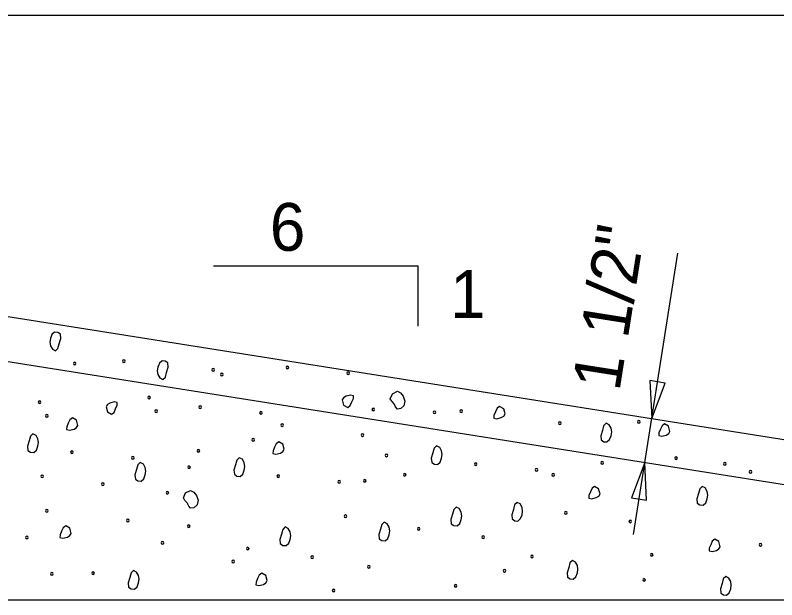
# Model space of a CAD drawing. Extents: x -439.1 to -407.9, y -458.1 to -436.2.
# Drawn here: x -421.545 to -419.155, y -448.319 to -446.484 of the extents above; entities that cross this region are included whole.
import ezdxf

# ---------------------------------------------------------------- set-up
doc = ezdxf.new("R2010")
doc.units = 0
doc.layers.add('Level 4', color=7, linetype='Continuous')
doc.layers.add('Level 45', color=7, linetype='Continuous')

msp = doc.modelspace()

# ---------------------------------------------------------------- linework, layer by layer
at = {"layer": 'Level 4'}
for p, q in [((-422.391, -446.484), (-416.8905, -446.484)), ((-423.8016, -447.0755), (-416.8905, -448.1707)), ((-419.6048, -448.1134), (-419.4651, -447.2309)), ((-420.9225, -447.2708), (-420.2799, -447.2708)), ((-420.2799, -447.4598), (-420.2799, -447.2708)), ((-421.8946, -447.5188), (-417.2694, -448.2521)), ((-423.8016, -448.3187), (-416.8905, -448.3187))]:
    msp.add_line(p, q, dxfattribs=at)
for points in [[(-421.4187, -447.5372), (-421.4108, -447.5297), (-421.407, -447.5151), (-421.4017, -447.4983), (-421.4031, -447.4852), (-421.4113, -447.4796), (-421.4213, -447.4788), (-421.4297, -447.4861), (-421.4343, -447.4982), (-421.4361, -447.51), (-421.4343, -447.5216), (-421.4283, -447.5324), (-421.4187, -447.5372)], [(-421.0817, -447.6272), (-421.0737, -447.6197), (-421.07, -447.6051), (-421.0647, -447.5883), (-421.0661, -447.5753), (-421.0743, -447.5697), (-421.0843, -447.5688), (-421.0927, -447.5761), (-421.0972, -447.5882), (-421.0991, -447.6), (-421.0972, -447.6116), (-421.0912, -447.6224), (-421.0817, -447.6272)], [(-419.5529, -447.631), (-419.5472, -447.7495), (-419.5052, -447.6386)], [(-420.5015, -447.7148), (-420.4937, -447.7089), (-420.4885, -447.6979), (-420.4838, -447.6867), (-420.4834, -447.6785), (-420.4928, -447.6761), (-420.5067, -447.6798), (-420.5145, -447.6845), (-420.5184, -447.6915), (-420.5142, -447.7074), (-420.5015, -447.7148)], [(-420.3678, -447.6877), (-420.3612, -447.672), (-420.3457, -447.6644), (-420.3354, -447.6692), (-420.3275, -447.6799), (-420.3218, -447.6952), (-420.3249, -447.7098), (-420.335, -447.7186), (-420.3457, -447.7202), (-420.3512, -447.7131), (-420.3561, -447.7033), (-420.3631, -447.6957), (-420.3678, -447.6877)], [(-421.2428, -447.7363), (-421.235, -447.7305), (-421.2298, -447.7195), (-421.225, -447.7082), (-421.2246, -447.7), (-421.2341, -447.6977), (-421.2479, -447.7013), (-421.2557, -447.7061), (-421.2596, -447.713), (-421.2554, -447.7289), (-421.2428, -447.7363)], [(-420.0246, -447.7119), (-420.0324, -447.7178), (-420.0376, -447.7288), (-420.0424, -447.74), (-420.0428, -447.7483), (-420.0333, -447.7506), (-420.0195, -447.747), (-420.0117, -447.7422), (-420.0078, -447.7353), (-420.012, -447.7194), (-420.0246, -447.7119)], [(-421.3656, -447.7479), (-421.3733, -447.7538), (-421.3785, -447.7648), (-421.3833, -447.776), (-421.3837, -447.7843), (-421.3743, -447.7866), (-421.3604, -447.783), (-421.3526, -447.7782), (-421.3487, -447.7713), (-421.3529, -447.7553), (-421.3656, -447.7479)], [(-419.6904, -447.7649), (-419.6983, -447.7724), (-419.7021, -447.787), (-419.7074, -447.8038), (-419.706, -447.8169), (-419.6978, -447.8225), (-419.6878, -447.8234), (-419.6794, -447.816), (-419.6748, -447.8039), (-419.673, -447.7921), (-419.6748, -447.7805), (-419.6808, -447.7697), (-419.6904, -447.7649)], [(-419.5071, -447.7667), (-419.5149, -447.7726), (-419.5201, -447.7836), (-419.5248, -447.7948), (-419.5253, -447.803), (-419.5158, -447.8054), (-419.5019, -447.8017), (-419.4941, -447.797), (-419.4902, -447.7901), (-419.4945, -447.7741), (-419.5071, -447.7667)], [(-421.4894, -447.798), (-421.4973, -447.8055), (-421.5011, -447.8201), (-421.5064, -447.8369), (-421.505, -447.8499), (-421.4968, -447.8555), (-421.4868, -447.8564), (-421.4784, -447.8491), (-421.4738, -447.837), (-421.472, -447.8252), (-421.4738, -447.8136), (-421.4798, -447.8028), (-421.4894, -447.798)], [(-420.7179, -447.823), (-420.7257, -447.8289), (-420.7309, -447.8399), (-420.7357, -447.8511), (-420.7361, -447.8594), (-420.7266, -447.8617), (-420.7127, -447.8581), (-420.705, -447.8533), (-420.701, -447.8464), (-420.7053, -447.8304), (-420.7179, -447.823)], [(-420.2223, -447.8356), (-420.2302, -447.843), (-420.2339, -447.8576), (-420.2393, -447.8744), (-420.2378, -447.8875), (-420.2296, -447.8931), (-420.2197, -447.894), (-420.2112, -447.8866), (-420.2067, -447.8745), (-420.2049, -447.8628), (-420.2067, -447.8511), (-420.2127, -447.8403), (-420.2223, -447.8356)], [(-420.8417, -447.8731), (-420.8497, -447.8805), (-420.8534, -447.8952), (-420.8587, -447.912), (-420.8573, -447.925), (-420.8491, -447.9306), (-420.8392, -447.9315), (-420.8307, -447.9241), (-420.8262, -447.9121), (-420.8243, -447.9003), (-420.8262, -447.8887), (-420.8322, -447.8779), (-420.8417, -447.8731)], [(-421.1524, -447.888), (-421.1603, -447.8955), (-421.164, -447.9101), (-421.1693, -447.9269), (-421.1679, -447.94), (-421.1597, -447.9456), (-421.1498, -447.9464), (-421.1413, -447.9391), (-421.1368, -447.927), (-421.1349, -447.9152), (-421.1368, -447.9036), (-421.1428, -447.8928), (-421.1524, -447.888)], [(-419.5634, -448.0061), (-419.5691, -447.8876), (-419.6111, -447.9986)], [(-419.7265, -447.9629), (-419.7343, -447.9688), (-419.7395, -447.9798), (-419.7442, -447.991), (-419.7447, -447.9993), (-419.7352, -448.0016), (-419.7213, -447.998), (-419.7135, -447.9932), (-419.7096, -447.9863), (-419.7139, -447.9704), (-419.7265, -447.9629)], [(-419.3887, -447.9631), (-419.3966, -447.9706), (-419.4003, -447.9852), (-419.4056, -448.002), (-419.4042, -448.0151), (-419.396, -448.0207), (-419.3861, -448.0215), (-419.3776, -448.0142), (-419.3731, -448.0021), (-419.3713, -447.9903), (-419.3731, -447.9787), (-419.3791, -447.9679), (-419.3887, -447.9631)], [(-421.0169, -447.9991), (-421.0103, -447.9834), (-420.9948, -447.9758), (-420.9845, -447.9806), (-420.9766, -447.9913), (-420.9709, -448.0066), (-420.974, -448.0212), (-420.9841, -448.03), (-420.9948, -448.0316), (-421.0003, -448.0245), (-421.0052, -448.0147), (-421.0122, -448.0071), (-421.0169, -447.9991)], [(-419.9698, -448.013), (-419.9777, -448.0205), (-419.9815, -448.0351), (-419.9868, -448.0519), (-419.9854, -448.065), (-419.9772, -448.0706), (-419.9672, -448.0715), (-419.9588, -448.0641), (-419.9542, -448.052), (-419.9524, -448.0402), (-419.9542, -448.0286), (-419.9602, -448.0178), (-419.9698, -448.013)], [(-420.1609, -448.028), (-420.1689, -448.0354), (-420.1726, -448.05), (-420.1779, -448.0668), (-420.1765, -448.0799), (-420.1683, -448.0855), (-420.1583, -448.0864), (-420.1499, -448.079), (-420.1454, -448.0669), (-420.1435, -448.0552), (-420.1454, -448.0435), (-420.1514, -448.0327), (-420.1609, -448.028)], [(-421.3866, -448.0869), (-421.3944, -448.0928), (-421.3996, -448.1038), (-421.4044, -448.115), (-421.4048, -448.1232), (-421.3953, -448.1256), (-421.3814, -448.1219), (-421.3737, -448.1172), (-421.3698, -448.1102), (-421.374, -448.0943), (-421.3866, -448.0869)], [(-420.3869, -448.0754), (-420.3948, -448.0829), (-420.3986, -448.0975), (-420.4039, -448.1143), (-420.4024, -448.1274), (-420.3943, -448.133), (-420.3843, -448.1338), (-420.3758, -448.1265), (-420.3713, -448.1144), (-420.3695, -448.1026), (-420.3713, -448.091), (-420.3773, -448.0802), (-420.3869, -448.0754)], [(-420.6975, -448.0903), (-420.7054, -448.0978), (-420.7092, -448.1124), (-420.7145, -448.1292), (-420.7131, -448.1423), (-420.7049, -448.1479), (-420.6949, -448.1488), (-420.6865, -448.1414), (-420.6819, -448.1293), (-420.6801, -448.1176), (-420.6819, -448.1059), (-420.6879, -448.0951), (-420.6975, -448.0903)], [(-419.3493, -448.1289), (-419.3571, -448.1348), (-419.3623, -448.1458), (-419.3671, -448.157), (-419.3675, -448.1652), (-419.358, -448.1676), (-419.3442, -448.1639), (-419.3364, -448.1592), (-419.3325, -448.1523), (-419.3367, -448.1363), (-419.3493, -448.1289)], [(-419.7961, -448.1957), (-419.804, -448.2031), (-419.8077, -448.2178), (-419.813, -448.2345), (-419.8116, -448.2476), (-419.8034, -448.2532), (-419.7935, -448.2541), (-419.785, -448.2467), (-419.7805, -448.2347), (-419.7787, -448.2229), (-419.7805, -448.2113), (-419.7865, -448.2005), (-419.7961, -448.1957)], [(-421.1734, -448.227), (-421.1814, -448.2344), (-421.1851, -448.2491), (-421.1904, -448.2658), (-421.189, -448.2789), (-421.1808, -448.2845), (-421.1708, -448.2854), (-421.1624, -448.278), (-421.1578, -448.2659), (-421.156, -448.2542), (-421.1578, -448.2426), (-421.1639, -448.2317), (-421.1734, -448.227)], [(-420.7715, -448.2353), (-420.7793, -448.2412), (-420.7845, -448.2522), (-420.7893, -448.2634), (-420.7897, -448.2716), (-420.7802, -448.274), (-420.7663, -448.2703), (-420.7586, -448.2656), (-420.7547, -448.2586), (-420.7589, -448.2427), (-420.7715, -448.2353)], [(-419.315, -448.2458), (-419.3229, -448.2532), (-419.3266, -448.2678), (-419.3319, -448.2846), (-419.3305, -448.2977), (-419.3223, -448.3033), (-419.3124, -448.3042), (-419.3039, -448.2968), (-419.2994, -448.2847), (-419.2975, -448.273), (-419.2994, -448.2613), (-419.3054, -448.2505), (-419.315, -448.2458)]]:
    msp.add_lwpolyline(points, close=True, dxfattribs=at)
for centre, start, end in [((-421.3585, -447.5773), 0, 180), ((-421.3585, -447.5773), 180, 0), ((-421.204, -447.5697), 0, 180), ((-421.204, -447.5697), 180, 0), ((-420.6908, -447.5897), 0, 180), ((-420.9239, -447.5973), 0, 180), ((-420.9239, -447.5973), 180, 0), ((-420.8968, -447.6116), 0, 180), ((-420.6908, -447.5897), 180, 0), ((-420.5001, -447.6072), 0, 180), ((-420.5001, -447.6072), 180, 0), ((-420.8968, -447.6116), 180, 0), ((-421.1251, -447.6837), 0, 180), ((-421.4685, -447.6987), 0, 180), ((-421.4685, -447.6987), 180, 0), ((-421.1251, -447.6837), 180, 0), ((-421.1026, -447.7265), 0, 180), ((-421.1026, -447.7265), 180, 0), ((-420.9645, -447.7145), 0, 180), ((-420.9645, -447.7145), 180, 0), ((-420.7737, -447.7321), 0, 180), ((-420.4211, -447.7212), 0, 180), ((-420.4211, -447.7212), 180, 0), ((-420.2292, -447.7304), 0, 180), ((-420.1451, -447.7268), 0, 180), ((-420.1451, -447.7268), 180, 0), ((-421.446, -447.7415), 0, 180), ((-421.446, -447.7415), 180, 0), ((-420.7737, -447.7321), 180, 0), ((-420.2292, -447.7304), 180, 0), ((-420.7073, -447.7702), 0, 180), ((-420.7073, -447.7702), 180, 0), ((-419.8354, -447.7641), 0, 180), ((-419.8354, -447.7641), 180, 0), ((-419.5875, -447.7603), 0, 180), ((-419.5875, -447.7603), 180, 0), ((-420.4549, -447.8016), 0, 180), ((-420.4549, -447.8016), 180, 0), ((-420.7983, -447.8166), 0, 180), ((-420.7983, -447.8166), 180, 0), ((-420.9702, -447.8511), 0, 180), ((-421.367, -447.8555), 0, 180), ((-421.367, -447.8555), 180, 0), ((-421.1762, -447.8731), 0, 180), ((-421.1762, -447.8731), 180, 0), ((-420.9702, -447.8511), 180, 0), ((-420.38, -447.8655), 0, 180), ((-420.38, -447.8655), 180, 0), ((-419.471, -447.8743), 0, 180), ((-420.0999, -447.8931), 0, 180), ((-420.0999, -447.8931), 180, 0), ((-419.7031, -447.8887), 0, 180), ((-419.7031, -447.8887), 180, 0), ((-419.471, -447.8743), 180, 0), ((-419.3178, -447.8918), 0, 180), ((-419.3178, -447.8918), 180, 0), ((-420.9995, -447.903), 0, 180), ((-420.9995, -447.903), 180, 0), ((-419.9091, -447.9106), 0, 180), ((-419.9091, -447.9106), 180, 0), ((-419.2373, -447.917), 0, 180), ((-419.2373, -447.917), 180, 0), ((-421.4602, -447.9313), 0, 180), ((-421.4602, -447.9313), 180, 0), ((-420.7194, -447.9306), 0, 180), ((-420.7194, -447.9306), 180, 0), ((-420.5286, -447.9481), 0, 180), ((-420.4481, -447.9451), 0, 180), ((-420.4481, -447.9451), 180, 0), ((-420.3226, -447.9262), 0, 180), ((-420.3226, -447.9262), 180, 0), ((-419.8568, -447.9264), 0, 180), ((-419.8568, -447.9264), 180, 0), ((-421.2702, -447.956), 0, 180), ((-421.2702, -447.956), 180, 0), ((-420.5286, -447.9481), 180, 0), ((-421.0676, -447.9827), 0, 180), ((-421.0676, -447.9827), 180, 0), ((-421.4456, -448.0392), 0, 180), ((-421.4456, -448.0392), 180, 0), ((-420.5087, -448.0568), 0, 180), ((-420.5087, -448.0568), 180, 0), ((-419.8171, -448.046), 0, 180), ((-419.8171, -448.046), 180, 0), ((-421.1913, -448.07), 0, 180), ((-421.1913, -448.07), 180, 0), ((-421.0005, -448.0875), 0, 180), ((-421.0005, -448.0875), 180, 0), ((-419.6145, -448.0727), 0, 180), ((-419.6145, -448.0727), 180, 0), ((-420.2788, -448.0959), 0, 180), ((-420.2788, -448.0959), 180, 0), ((-421.5089, -448.1237), 0, 180), ((-421.5089, -448.1237), 180, 0), ((-421.0831, -448.1398), 0, 180), ((-420.0762, -448.1226), 0, 180), ((-420.0762, -448.1226), 180, 0), ((-421.0831, -448.1398), 180, 0), ((-420.8153, -448.1583), 0, 180), ((-420.8153, -448.1583), 180, 0), ((-419.2057, -448.1458), 0, 180), ((-419.2057, -448.1458), 180, 0), ((-420.6128, -448.185), 0, 180), ((-419.9231, -448.1832), 0, 180), ((-419.9231, -448.1832), 180, 0), ((-419.5474, -448.1775), 0, 180), ((-419.5474, -448.1775), 180, 0), ((-420.8612, -448.1988), 0, 180), ((-420.8612, -448.1988), 180, 0), ((-420.6128, -448.185), 180, 0), ((-421.3009, -448.235), 0, 180), ((-420.4355, -448.2149), 0, 180), ((-420.4355, -448.2149), 180, 0), ((-420.0091, -448.2275), 0, 180), ((-420.0091, -448.2275), 180, 0), ((-421.4299, -448.2377), 0, 180), ((-421.4299, -448.2377), 180, 0), ((-421.3009, -448.235), 180, 0), ((-419.5715, -448.2565), 0, 180), ((-420.1628, -448.2752), 0, 180), ((-420.1628, -448.2752), 180, 0), ((-419.5715, -448.2565), 180, 0), ((-420.5456, -448.2898), 0, 180), ((-420.5456, -448.2898), 180, 0)]:
    msp.add_arc(centre, 0.00416, start, end, dxfattribs=at)

# ---------------------------------------------------------------- texts
for s, p in [('6', (-420.7459, -447.2234)), ('1', (-420.1803, -447.4341))]:
    msp.add_text(s, height=0.15, dxfattribs=at).set_placement(p)
at = {"layer": 'Level 45'}
msp.add_text('1 1/2"', height=0.15, rotation=81, dxfattribs=at).set_placement((-419.6489, -447.6676))

doc.saveas('drawing.dxf')
